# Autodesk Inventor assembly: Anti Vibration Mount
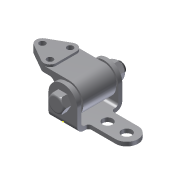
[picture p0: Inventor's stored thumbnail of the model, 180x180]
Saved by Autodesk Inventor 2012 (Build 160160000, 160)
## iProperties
Created: 2011-07
Part Number: Anti Vibration Mount
Document SubType Name: Assembly
Designer: CadCim
Author: CadCim
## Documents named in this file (5)
- C:\Users\CadCim\Documents\SAILESH\inventor-2011-fact-prt\c09_inv_2011-prt\c09_inv_2012_prt\Tutorials\c09_tut03_inv\Anti Vibration Mount\Anti Vibration Mount.iam
- C:\Users\CadCim\Documents\SAILESH\inventor-2011-fact-prt\c09_inv_2011-prt\c09_inv_2012_prt\Tutorials\c09_tut03_inv\Anti Vibration Mount\Yoke Plate.ipt
- C:\Users\CadCim\Documents\SAILESH\inventor-2011-fact-prt\c09_inv_2011-prt\c09_inv_2012_prt\Tutorials\c09_tut03_inv\Anti Vibration Mount\Body-Bushing Ruber.iam
- C:\Users\CadCim\Documents\SAILESH\inventor-2011-fact-prt\c09_inv_2011-prt\c09_inv_2012_prt\Tutorials\c09_tut03_inv\Anti Vibration Mount\Hex Bolt.ipt
- C:\Users\CadCim\Documents\SAILESH\inventor-2011-fact-prt\c09_inv_2011-prt\c09_inv_2012_prt\Tutorials\c09_tut03_inv\Anti Vibration Mount\Nut.ipt
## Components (4 placed, 4 different names)
1. Yoke Plate:1 — Insert:1, Angle:1, Insert:2, Mate:1
2. Body-Bushing Ruber:1 [sub-assembly] — Insert:1, Angle:1, Angle:2
3. Hex Bolt:1 — Insert:2, Angle:2, Mate:2
4. Nut:1 — Mate:1, Mate:2
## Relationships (6: Insert 2, Angle 2, Mate 2)
- Insert:1: Yoke Plate:1 ↔ Body-Bushing Ruber:1
- Angle:1: Yoke Plate:1 ↔ Body-Bushing Ruber:1
- Insert:2: Yoke Plate:1 ↔ Hex Bolt:1
- Angle:2: Body-Bushing Ruber:1 ↔ Hex Bolt:1
- Mate:1: Yoke Plate:1 ↔ Nut:1
- Mate:2: Hex Bolt:1 ↔ Nut:1
